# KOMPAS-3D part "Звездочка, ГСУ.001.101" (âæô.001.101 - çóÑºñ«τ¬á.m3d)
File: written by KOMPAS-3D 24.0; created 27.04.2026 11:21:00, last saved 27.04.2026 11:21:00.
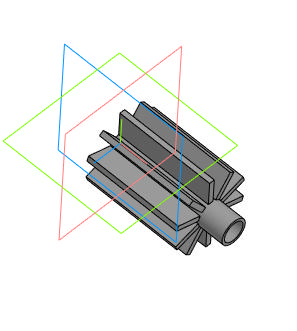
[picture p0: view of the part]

Document properties: Автор: User7; Полное имя файла: C:\Users\User7\Desktop\Двигатель мясорубки\ГСУ.001.101 - Звездочка.m3d

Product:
- Body: Тело 1  | qty 1
    Масса: 0.010662
- Body: Тело 3  | qty 1  | 10 such rows
    Масса: 0.005971
- Part/product: Звездочка  | designation ГСУ.001.101
    Масса: 0.070368

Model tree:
1. Эскиз:1
2. Элемент выдавливания:1
     Расстояние 1 = 48
3. Эскиз:2  (with: Грань.Элемент выдавливания:1, Ребро.Элемент выдавливания:1)
4. Листовое тело:1
     Расстояние 1 = 10; Толщина листового тела = 38; Радиус сгиба = 5
5. Массив по концентрической сетке:1  (2 pattern instances)
6. Тело 3  (with: Грань.Элемент выдавливания:1)  (8 pattern instances)
     N 1 = 1; Шаг 1 = 10; Шаг 2 = 360; Номер 1 = 1

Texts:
  ГСУ.001.101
